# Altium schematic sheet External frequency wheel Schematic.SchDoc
size A4
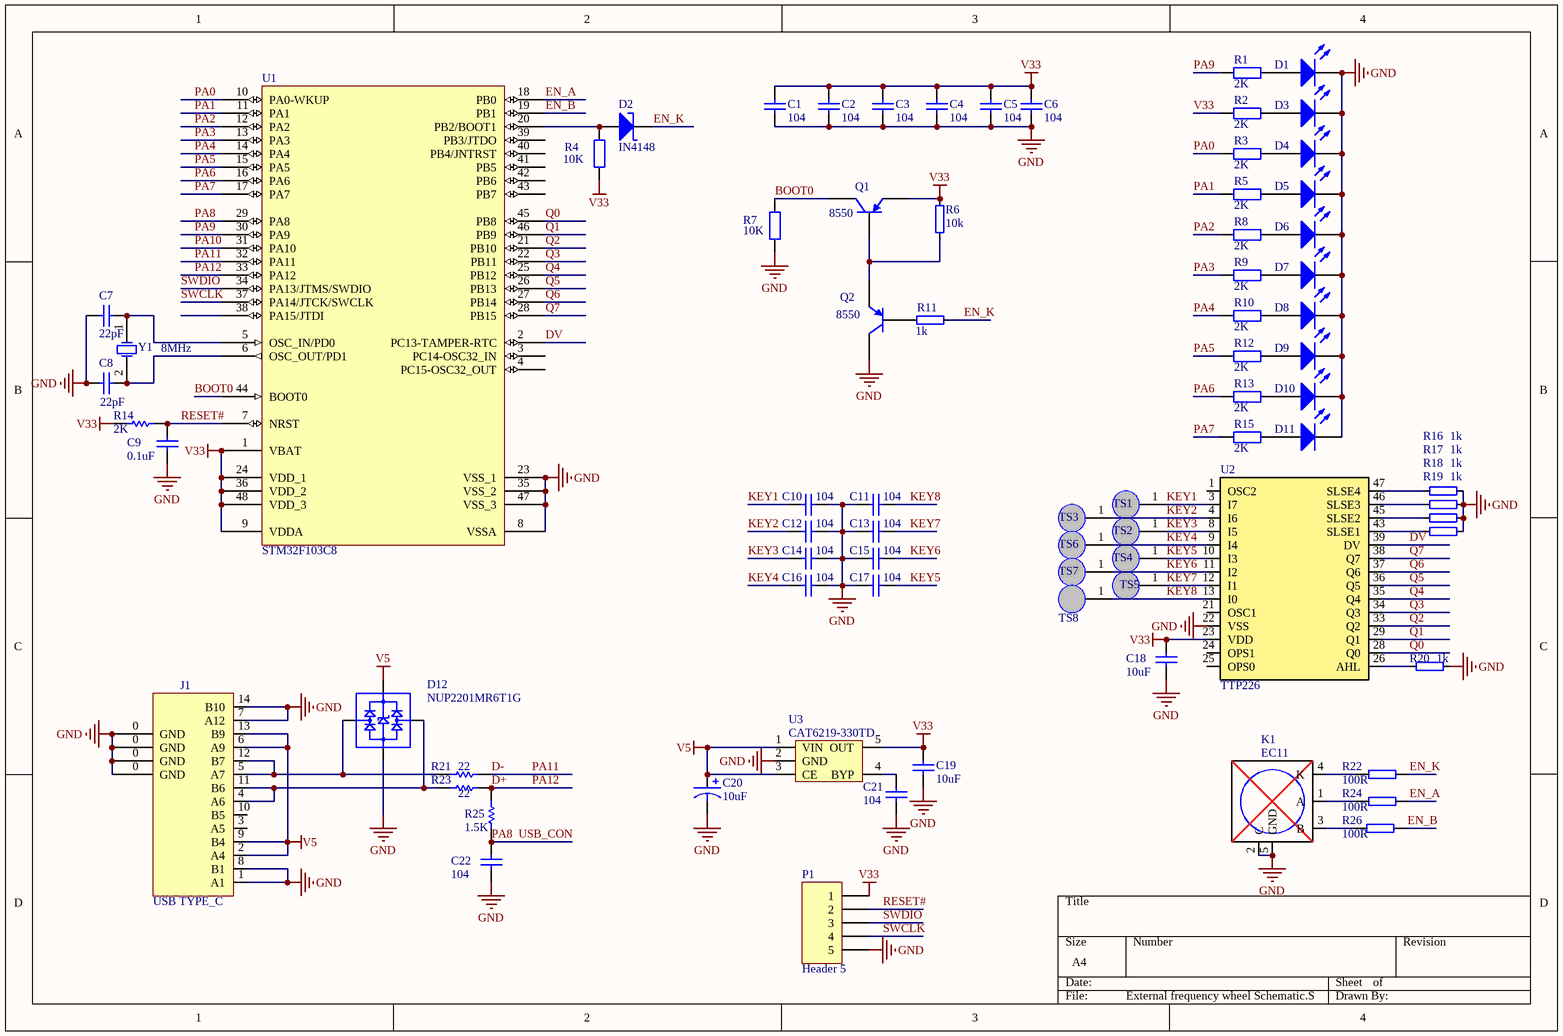
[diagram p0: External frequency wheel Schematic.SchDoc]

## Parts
C1  value 104  [CAP0805(2512)]  (hidden comment: Cap)
C2  value 104  [CAP0805(2512)]  (hidden comment: Cap)
C3  value 104  [CAP0805(2512)]  (hidden comment: Cap)
C4  value 104  [CAP0805(2512)]  (hidden comment: Cap)
C5  value 104  [CAP0805(2512)]  (hidden comment: Cap)
C6  value 104  [CAP0805(2512)]  (hidden comment: Cap)
C7  value 22pF  [CAP0805(2512)]  (hidden comment: Cap)
C8  value 22pF  [CAP0805(2512)]  (hidden comment: Cap)
C9  value 0.1uF  [CAP0805(2512)]  (hidden comment: Cap)
C10  104  [CAP0805(2512)]
C11  104  [CAP0805(2512)]
C12  104  [CAP0805(2512)]
C13  104  [CAP0805(2512)]
C14  104  [CAP0805(2512)]
C15  104  [CAP0805(2512)]
C16  104  [CAP0805(2512)]
C17  104  [CAP0805(2512)]
C18  value 10uF  [CAP0805(2512)]  (hidden comment: Cap)
C19  value 10uF  [CAP0805(2512)]  (hidden comment: Cap)
C20  10uF  [C3216]
C21  104  [C0402]
C22  104  [CAP0805(2512)]
D1  LED0  [DIODE_100mil]  (value not drawn)
D2  IN4148  [SOD523]
D3  LED0  [DIODE_100mil]  (value not drawn)
D4  LED0  [DIODE_100mil]  (value not drawn)
D5  LED0  [DIODE_100mil]  (value not drawn)
D6  LED0  [DIODE_100mil]  (value not drawn)
D7  LED0  [DIODE_100mil]  (value not drawn)
D8  LED0  [DIODE_100mil]  (value not drawn)
D9  LED0  [DIODE_100mil]  (value not drawn)
D10  LED0  [DIODE_100mil]  (value not drawn)
D11  LED0  [DIODE_100mil]  (value not drawn)
D12  NUP2201MR6T1G  [SOT-23-6A]
J1  USB TYPE_C  [USB-C-TH_TYPE-C3.1-USB-8]
K1  EC11  [EC11卧式]
P1  Header 5  [HDR1X5]
Q1  8550  [SOT-23]
Q2  8550  [SOT-23]
R1  value 2K  [RES0805(2012M)]  (hidden comment: Res2)
R2  value 2K  [RES0805(2012M)]  (hidden comment: Res2)
R3  value 2K  [RES0805(2012M)]  (hidden comment: Res2)
R4  10K  [R0402]
R5  value 2K  [RES0805(2012M)]  (hidden comment: Res2)
R6  10k  [R0603]
R7  10K  [R0402]
R8  value 2K  [RES0805(2012M)]  (hidden comment: Res2)
R9  value 2K  [RES0805(2012M)]  (hidden comment: Res2)
R10  value 2K  [RES0805(2012M)]  (hidden comment: Res2)
R11  1k  [R0603]
R12  value 2K  [RES0805(2012M)]  (hidden comment: Res2)
R13  value 2K  [RES0805(2012M)]  (hidden comment: Res2)
R14  value 2K  [RES0805(2012M)]  (hidden comment: Res Semi)
R15  value 2K  [RES0805(2012M)]  (hidden comment: Res2)
R16  1k  [R0603]
R17  1k  [R0603]
R18  1k  [R0603]
R19  1k  [R0603]
R20  1k  [R0603]
R21  value 22  [RES0805(2012M)]  (hidden comment: Res Semi)
R22  100R  [0603A]
R23  value 22  [RES0805(2012M)]  (hidden comment: Res Semi)
R24  100R  [0603A]
R25  1.5K  [RES0805(2012M)]
R26  100R  [0603A]
TS1  12x16  [TS-H-12x16]  (value not drawn)
TS2  12x16  [TS-H-12x16]  (value not drawn)
TS3  12x16  [TS-H-12x16]  (value not drawn)
TS4  12x16  [TS-H-12x16]  (value not drawn)
TS5  12x16  [TS-H-12x16]  (value not drawn)
TS6  12x16  [TS-H-12x16]  (value not drawn)
TS7  12x16  [TS-H-12x16]  (value not drawn)
TS8  12x16  [TS-H-12x16]  (value not drawn)
U1  STM32F103C8  [LQFP48 7X7_M]
U2  TTP226
U3  CAT6219-330TD  [SOT23-5]
Y1  8MHz  [XTAL_0.4]

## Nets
GND: C1.1 C2.1 C3.1 C4.1 C5.1 C6.1 C7.1 C8.1 C9.2 C10.1 C11.2 C12.1 C13.2 C14.1 C15.2 C16.1 C17.2 C18.1 C19.1 C20.2 C21.1 C22.2 D1.2(K) D3.2(K) D4.2(K) D5.2(K) D6.2(K) D7.2(K) D8.2(K) D9.2(K) D10.2(K) D11.2(K) D12.2 J1.0(GND) J1.1(A1) J1.7(A12) J1.8(B1) J1.14(B10) K1.2(C) K1.5(GND) P1.5 Q2.3(C) R7.1 R16.2 R17.2 R18.2 R19.2 R20.2 U1.8(VSSA) U1.23(VSS_1) U1.35(VSS_2) U1.47(VSS_3) U2.22(VSS) U3.2(GND)
V5: C20.1 D12.5 J1.2(A4) J1.6(A9) J1.9(B4) J1.13(B9) U3.1(VIN) U3.3(CE)
V33: C1.2 C2.2 C3.2 C4.2 C5.2 C6.2 C18.2 C19.2 P1.1 Q1.2(E) R2.1 R4.1 R6.2 R14.1 U1.1(VBAT) U1.9(VDDA) U1.24(VDD_1) U1.36(VDD_2) U1.48(VDD_3) U2.23(VDD) U3.5(OUT)
BOOT0: Q1.3(C) R7.2 U1.44(BOOT0)
D+: R23.2 R25.2 U1.33(PA12)  [also labelled PA12]
D-: R21.2 U1.32(PA11)  [also labelled PA11]
DV: U1.2(PC13-TAMPER-RTC) U2.39(DV)
EN_A: R24.2 U1.18(PB0)
EN_B: R26.2 U1.19(PB1)
EN_K: D2.2 R11.2 R22.2
KEY1: C10.2 TS1.1 U2.3(I7)
KEY2: C12.2 TS3.1 U2.4(I6)
KEY3: C14.2 TS2.1 U2.8(I5)
KEY4: C16.2 TS6.1 U2.9(I4)
KEY5: C17.1 TS4.1 U2.10(I3)
KEY6: C15.1 TS8.1 U2.11(I2)
KEY7: C13.1 TS5.1 U2.12(I1)
KEY8: C11.1 TS7.1 U2.13(I0)
PA0: R3.1 U1.10(PA0-WKUP)
PA1: R5.1 U1.11(PA1)
PA2: R8.1 U1.12(PA2)
PA3: R9.1 U1.13(PA3)
PA4: R10.1 U1.14(PA4)
PA5: R12.1 U1.15(PA5)
PA6: R13.1 U1.16(PA6)
PA7: R15.1 U1.17(PA7)
PA8: C22.1 R25.1 U1.29(PA8)  [also labelled USB_CON]
PA9: R1.1 U1.30(PA9)
PA10: U1.31(PA10)
Q0: U1.45(PB8) U2.28(Q0)
Q1: U1.46(PB9) U2.29(Q1)
Q2: U1.21(PB10) U2.33(Q2)
Q3: U1.22(PB11) U2.34(Q3)
Q4: U1.25(PB12) U2.35(Q4)
Q5: U1.26(PB13) U2.36(Q5)
Q6: U1.27(PB14) U2.37(Q6)
Q7: U1.28(PB15) U2.38(Q7)
RESET#: C9.1 P1.2 R14.2 U1.7(NRST)
SWCLK: P1.4 U1.37(PA14/JTCK/SWCLK)
SWDIO: P1.3 U1.34(PA13/JTMS/SWDIO)
NetC7_2: C7.2 U1.5(OSC_IN/PD0) Y1.1(OSC1)
NetC8_2: C8.2 U1.6(OSC_OUT/PD1) Y1.2(OSC2)
NetC21_2: C21.2 U3.4(BYP)
NetD1_1: D1.1(A) R1.2
NetD2_1: D2.1 R4.2 U1.20(PB2/BOOT1)
NetD3_1: D3.1(A) R2.2
NetD4_1: D4.1(A) R3.2
NetD5_1: D5.1(A) R5.2
NetD6_1: D6.1(A) R8.2
NetD7_1: D7.1(A) R9.2
NetD8_1: D8.1(A) R10.2
NetD9_1: D9.1(A) R12.2
NetD10_1: D10.1(A) R13.2
NetD11_1: D11.1(A) R15.2
NetD12_1: D12.1 J1.4(A6) J1.11(B6) R23.1
NetD12_6: D12.6 J1.5(A7) J1.12(B7) R21.1
NetK1_1: K1.1(A) R24.1
NetK1_3: K1.3(B) R26.1
NetK1_4: K1.4(K) R22.1
NetQ1_1: Q1.1(B) Q2.2(E) R6.1
NetQ2_1: Q2.1(B) R11.1
NetR16_1: R16.1 U2.47(SLSE4)
NetR17_1: R17.1 U2.46(SLSE3)
NetR18_1: R18.1 U2.45(SLSE2)
NetR19_1: R19.1 U2.43(SLSE1)
NetR20_1: R20.1 U2.26(AHL)

Not connected (* = marked no-connect by the designer): D12 3 4; J1 3(A5) 10(B5); U1 3(PC14-OSC32_IN) 4(PC15-OSC32_OUT) 38(PA15/JTDI) 39(PB3/JTDO) 40(PB4/JNTRST) 41(PB5) 42(PB6) 43(PB7); U2 1(OSC2) 21(OSC1) 24(OPS1) 25(OPS0)

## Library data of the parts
C1-C19 = Cap: Capacitor
C20 = CAP-E: Capacitor
C21 = Cap: 电容
C22 = Cap: Capacitor; Value: 0.1uF
D1 D3-D11 = LED0: Typical INFRARED GaAs LED
D2 = Diode_IN5822/5819: Diode_IN5822
D12 = NUP2201: TSOP?6 LOW CAPACITANCE  DIODE TVS ARRAY ,500 WATTS PEAK POWER ,6 VOLTS
P1 = Header 5: Header, 5-Pin
Q1 Q2 = PNP: PNP Bipolar Transistor
R1-R3 R5 R8-R10 R12 R13 R15 = Res2: Resistor
R4 R7 = Res: 电阻; Value: 1K
R6 R11 R16-R20 = RES
R14 R21 R23 R25 = Res Semi: Semiconductor Resistor
R22 R24 R26 = RES-1
TS1-TS8 = TTS: 触控弹簧; 版权归属: 源创客
U1 = STM32F103C8: Flaah:64/RAM:20/IO:36; BOM名称: 32位STM单片机; 版权归属: 源创客
U3 = CAT6219-: 3.3V 500mA LDO
Y1 = XTAL: Crystal Oscillator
